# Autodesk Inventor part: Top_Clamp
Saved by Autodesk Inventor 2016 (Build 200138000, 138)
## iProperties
Created: 2016-01
Part Number: Top_Clamp
Material: Generic
Document SubType Name: Modeling
Designer: John
Density: 1 g/cm^3
Appearance: Default
Author: John
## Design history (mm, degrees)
feature "Base1"
body "Solid1"
